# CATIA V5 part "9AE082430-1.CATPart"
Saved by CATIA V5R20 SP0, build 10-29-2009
Part number: 9AE082430-1
Revision: ANY
Definition: UNKNOWN
Nomenclature: 9AE082430-1
Source: Unknown
Bounding box of the stored display mesh (mm): x -8.5 to 8.5, y -0.001 to 76.999, z -8.5 to 8.5
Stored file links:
  C:\Users\Utente\Desktop\IO LAVORO\3D X SITO CF\CUMSA\3D files AE\AE 082430\9AE082430-1.CATPart
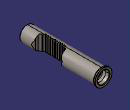
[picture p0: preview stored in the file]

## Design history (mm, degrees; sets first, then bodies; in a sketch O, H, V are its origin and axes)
Body1 "Chaflán2" (main body)
  Solid1: solid without history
